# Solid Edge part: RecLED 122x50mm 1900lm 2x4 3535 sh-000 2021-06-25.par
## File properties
Author: radoslaw.kuczynski
Template: iso metric part.par
Last saved by: radoslaw.kuczynski
Revision: 1
Application: Solid Edge
Gęstość: 0,000 kg/m^3
Dokładność: 0,990
Username: radoslaw.kuczynski
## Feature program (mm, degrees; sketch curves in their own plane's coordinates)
body "unnamed Body 1"
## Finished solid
Body 1: solid body, 775 faces, 2001 edges, 1258 vertices, 2 separate solids.
  Faces by surface: plane 463, cylinder 156, spline 80, cone 26, torus 19, sphere 18, spun 7, swept 6
  Edges by curve: line 1292, curve on surface 296, circle 271, ellipse 66, intersection 38, spline 38
Bounding box of the edges (mm; curved faces can reach further): 49.500 x 5.000 x 121.400, from (-24.75, -3.5, -60.7) to (24.75, 1.5, 60.7).
Cylindrical faces by radius (mm): R0.15 x16, R0.2 x39, R0.2002 x2, R0.2169 x3, R0.25 x12, R0.3 x2, R0.3373 x3, R0.4 x8, R0.4006 x2, R0.4008 x2, R0.525 x2, R0.6 x12, R0.65 x16, R0.75 x1, R1 x7, R1.05 x8, R1.0894 x2, R1.1 x14, R1.75 x2, R1.7689 x1, R3 x1, R3.05 x1
Conical faces (half-angle, radius in mm at the cone's reference point): 0.5 deg R0.5056 x4, 0.5 deg R1.0082 x4, 1 deg R0.5511 x2, 10 deg R0.2132 x2, 10 deg R0.4132 x2, 18.4844 deg R1.0657 x4, 27.363 deg R0.6214 x2, 45 deg R0.575 x2, 45 deg R0.625 x4
Toroidal faces (ring radius, tube radius in mm): R0.1 r0.2 x1, R0.8 r0.2 x4, R0.8522 r0.3 x2, R0.9002 r0.2 x1, R0.9018 r0.2 x1, R1.3 r0.2 x2, R1.8254 r0.13 x8
Spherical faces by radius (mm): R0.2 x8, R0.6 x2, R1.7 x8
Planar faces by outward normal: +x 52, +y 20, +z 58, -x 50, -y 68, -z 64, oblique 151
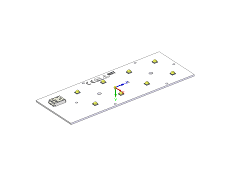
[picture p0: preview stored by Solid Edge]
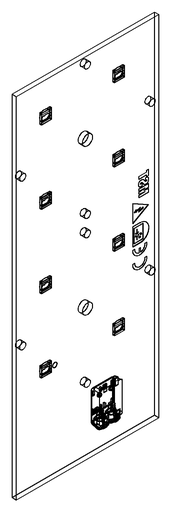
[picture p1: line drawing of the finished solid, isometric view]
